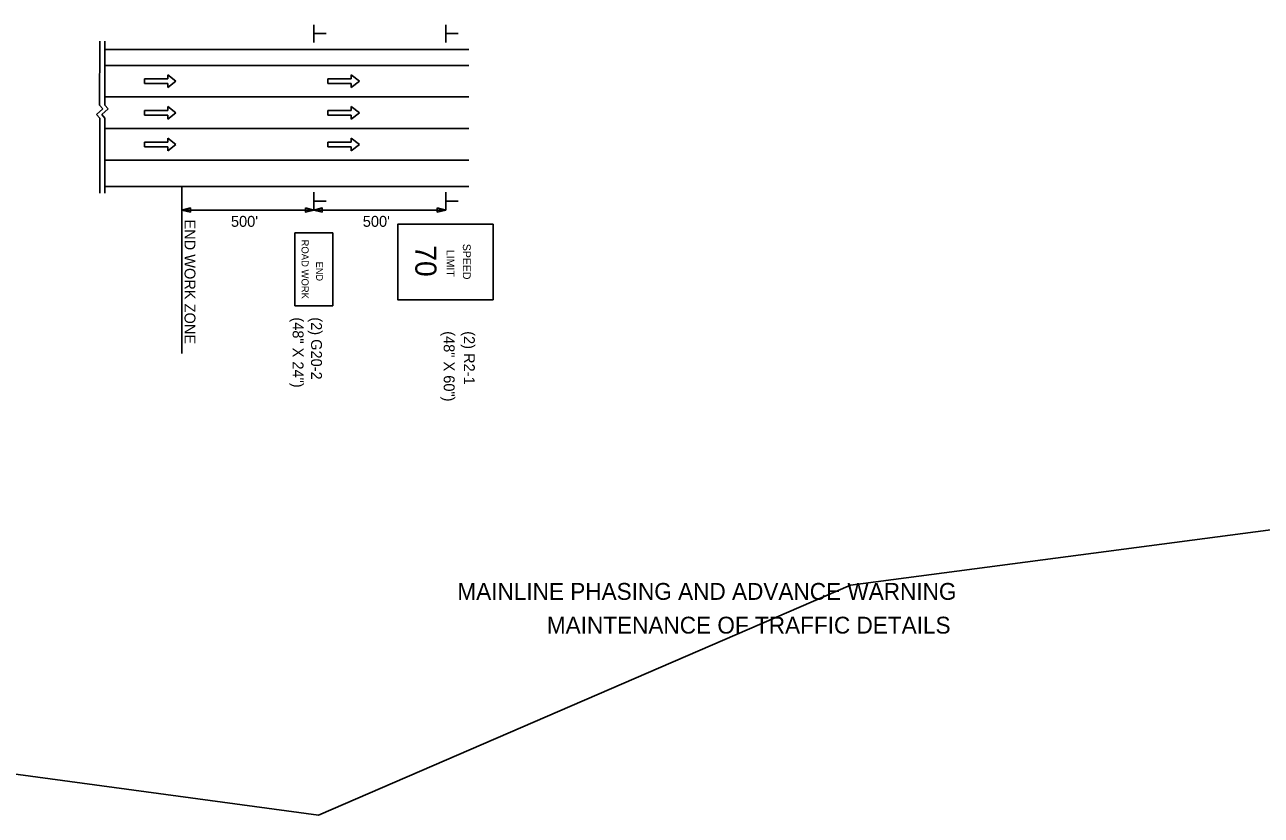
# Model space of a CAD drawing. Extents: x 1017892 to 1236694, y 658553 to 792468.
# Drawn here: x 1023101 to 1024859, y 658553 to 659677 of the extents above; entities that cross this region are included whole.
import ezdxf

# ---------------------------------------------------------------- set-up
doc = ezdxf.new("R2010")
doc.units = 0
for name, color, linetype in [('Default', 7, 'Continuous'), ('Level 1', 7, 'Continuous'), ('Level 3', 7, 'Continuous'), ('Level 42', 7, 'Continuous'), ('Level 8', 7, 'Continuous'), ('R_Border', 7, 'Continuous'), ('R_Const Phase All', 7, 'Continuous'), ('R_Proposed Road Annot', 7, 'Continuous')]:
    doc.layers.add(name, color=color, linetype=linetype)

msp = doc.modelspace()

# ---------------------------------------------------------------- linework, layer by layer
at = {"layer": 'Level 1'}
for p, q in [((1023304.1, 659600.3), (1023271, 659600.3)), ((1023271, 659600.3), (1023271, 659593.6)), ((1023304.1, 659593.6), (1023271, 659593.6)), ((1023304.1, 659606), (1023304.1, 659600.3)), ((1023304.1, 659606), (1023315.8, 659597)), ((1023315.8, 659597), (1023304.1, 659588)), ((1023304.1, 659593.6), (1023304.1, 659588)), ((1023565, 659600.3), (1023531.9, 659600.3)), ((1023531.9, 659600.3), (1023531.9, 659593.6)), ((1023565, 659593.6), (1023531.9, 659593.6)), ((1023565, 659606), (1023565, 659600.3)), ((1023565, 659606), (1023576.7, 659597)), ((1023576.7, 659597), (1023565, 659588)), ((1023565, 659593.6), (1023565, 659588)), ((1023304.1, 659555.3), (1023271, 659555.3)), ((1023271, 659555.3), (1023271, 659548.6)), ((1023304.1, 659561), (1023304.1, 659555.3)), ((1023304.1, 659561), (1023315.8, 659552)), ((1023565, 659555.3), (1023531.9, 659555.3)), ((1023531.9, 659555.3), (1023531.9, 659548.6)), ((1023565, 659561), (1023565, 659555.3)), ((1023565, 659561), (1023576.7, 659552)), ((1023304.1, 659548.6), (1023271, 659548.6)), ((1023315.8, 659552), (1023304.1, 659543)), ((1023304.1, 659548.6), (1023304.1, 659543)), ((1023565, 659548.6), (1023531.9, 659548.6)), ((1023576.7, 659552), (1023565, 659543)), ((1023565, 659548.6), (1023565, 659543)), ((1023304.1, 659510.3), (1023271, 659510.3)), ((1023271, 659510.3), (1023271, 659503.6)), ((1023304.1, 659503.6), (1023271, 659503.6)), ((1023304.1, 659516), (1023304.1, 659510.3)), ((1023304.1, 659516), (1023315.8, 659507)), ((1023315.8, 659507), (1023304.1, 659498)), ((1023304.1, 659503.6), (1023304.1, 659498)), ((1023565, 659510.3), (1023531.9, 659510.3)), ((1023531.9, 659510.3), (1023531.9, 659503.6)), ((1023565, 659503.6), (1023531.9, 659503.6)), ((1023565, 659516), (1023565, 659510.3)), ((1023565, 659516), (1023576.7, 659507)), ((1023576.7, 659507), (1023565, 659498)), ((1023565, 659503.6), (1023565, 659498))]:
    msp.add_line(p, q, dxfattribs=at)
at = {"layer": 'Level 3'}
for p, q in [((1023511.9, 659652), (1023511.9, 659677.3)), ((1023699.4, 659652), (1023699.4, 659677.3)), ((1023512.2, 659664.6), (1023529.5, 659664.6)), ((1023699.7, 659664.6), (1023717, 659664.6)), ((1023511.9, 659413.7), (1023511.9, 659439)), ((1023699.4, 659413.7), (1023699.4, 659439)), ((1023512.2, 659426.2), (1023529.5, 659426.2)), ((1023699.7, 659426.2), (1023717, 659426.2))]:
    msp.add_line(p, q, dxfattribs=at)
at = {"layer": 'Level 8'}
for p, q in [((1023485, 659277.5), (1023485, 659381.1)), ((1023485, 659381.1), (1023538.7, 659381.1)), ((1023538.7, 659277.5), (1023538.7, 659381.1)), ((1023485, 659277.5), (1023538.7, 659277.5))]:
    msp.add_line(p, q, dxfattribs=at)
msp.add_lwpolyline([(1023766.7, 659286.1), (1023631.3, 659286.1), (1023631.3, 659393.5), (1023766.7, 659393.5)], close=True, dxfattribs=at)
at = {"layer": 'R_Border'}
for points in [[(1024274.9, 658880.1), (1025124.6, 658991.8), (1027681.8, 658867.5)], [(1022936.9, 658631.4), (1023518.7, 658552.8), (1024274.9, 658880.1)]]:
    msp.add_lwpolyline(points, dxfattribs=at)
at = {"layer": 'R_Const Phase All'}
for p, q in [((1023207.3, 659562.8), (1023207.4, 659653.8)), ((1023214.8, 659562.8), (1023214.9, 659653.8)), ((1023732.4, 659642), (1023214.9, 659642)), ((1023732.4, 659619.5), (1023214.9, 659619.5)), ((1023732.4, 659574.5), (1023214.9, 659574.5)), ((1023211.8, 659557.6), (1023202.9, 659549.8)), ((1023211.8, 659557.6), (1023207.3, 659562.8)), ((1023219.3, 659557.6), (1023210.4, 659549.8)), ((1023219.3, 659557.6), (1023214.8, 659562.8)), ((1023207.4, 659544.6), (1023202.9, 659549.8)), ((1023207.4, 659437.8), (1023207.4, 659544.6)), ((1023214.9, 659544.6), (1023210.4, 659549.8)), ((1023214.9, 659437.8), (1023214.9, 659544.6)), ((1023732.4, 659529.5), (1023214.9, 659529.5)), ((1023732.4, 659484.5), (1023214.9, 659484.5)), ((1023732.4, 659447), (1023214.9, 659447))]:
    msp.add_line(p, q, dxfattribs=at)
at = {"layer": 'R_Proposed Road Annot'}
msp.add_line((1023324.4, 659209.4), (1023324.4, 659447.4), dxfattribs=at)
for points in [[(1023336.4, 659410.7), (1023324.4, 659413.7), (1023336.4, 659416.7)], [(1023499.9, 659416.7), (1023511.9, 659413.7), (1023499.9, 659410.7)], [(1023523.9, 659410.7), (1023511.9, 659413.7), (1023523.9, 659416.7)], [(1023687.4, 659416.7), (1023699.4, 659413.7), (1023687.4, 659410.7)]]:
    msp.add_lwpolyline(points, close=True, dxfattribs=at)
for points in [[(1023324.4, 659413.7), (1023511.9, 659413.7)], [(1023511.9, 659413.7), (1023699.4, 659413.7)]]:
    msp.add_lwpolyline(points, dxfattribs=at)

# ---------------------------------------------------------------- texts
at = {"layer": 'Default'}
for s, p in [('MAINLINE PHASING AND ADVANCE WARNING ', (1023716, 658859.2)), ('MAINTENANCE OF TRAFFIC DETAILS', (1023843.2, 658811.2))]:
    msp.add_text(s, height=24, rotation=360, dxfattribs=at).set_placement(p)
at = {"layer": 'Level 3'}
msp.add_text('ROAD WORK', height=10.07, rotation=270, dxfattribs=at).set_placement((1023494.4, 659371.7))
at = {"layer": 'Level 42'}
msp.add_text('END', height=9.76, rotation=270, dxfattribs=at).set_placement((1023515.1, 659340.2))
at = {"layer": 'Level 8'}
for s, height, rotation, p in [('70', 30, 270, (1023656.2, 659363.5)), ('SPEED', 11.19, 270, (1023723.8, 659365.6)), ('LIMIT', 11.19, 270, (1023700.6, 659357)), ('(48" X 24")', 15.5, 270.0004, (1023481.7, 659261)), ('(2) G20-2', 15.5, 270.0004, (1023507.9, 659261.1)), ('(48" X 60")', 15.5, 270, (1023696.6, 659241.3)), ('(2) R2-1', 15.5, 270, (1023725.3, 659241.3))]:
    msp.add_text(s, height=height, rotation=rotation, dxfattribs=at).set_placement(p)
at = {"layer": 'R_Proposed Road Annot'}
msp.add_text('END WORK ZONE', height=15.5, rotation=270, dxfattribs=at).set_placement((1023328, 659400.3))
for p in [(1023394, 659389.8), (1023581.5, 659389.8)]:
    msp.add_text("500'", height=15.5, dxfattribs=at).set_placement(p)

doc.saveas('drawing.dxf')
